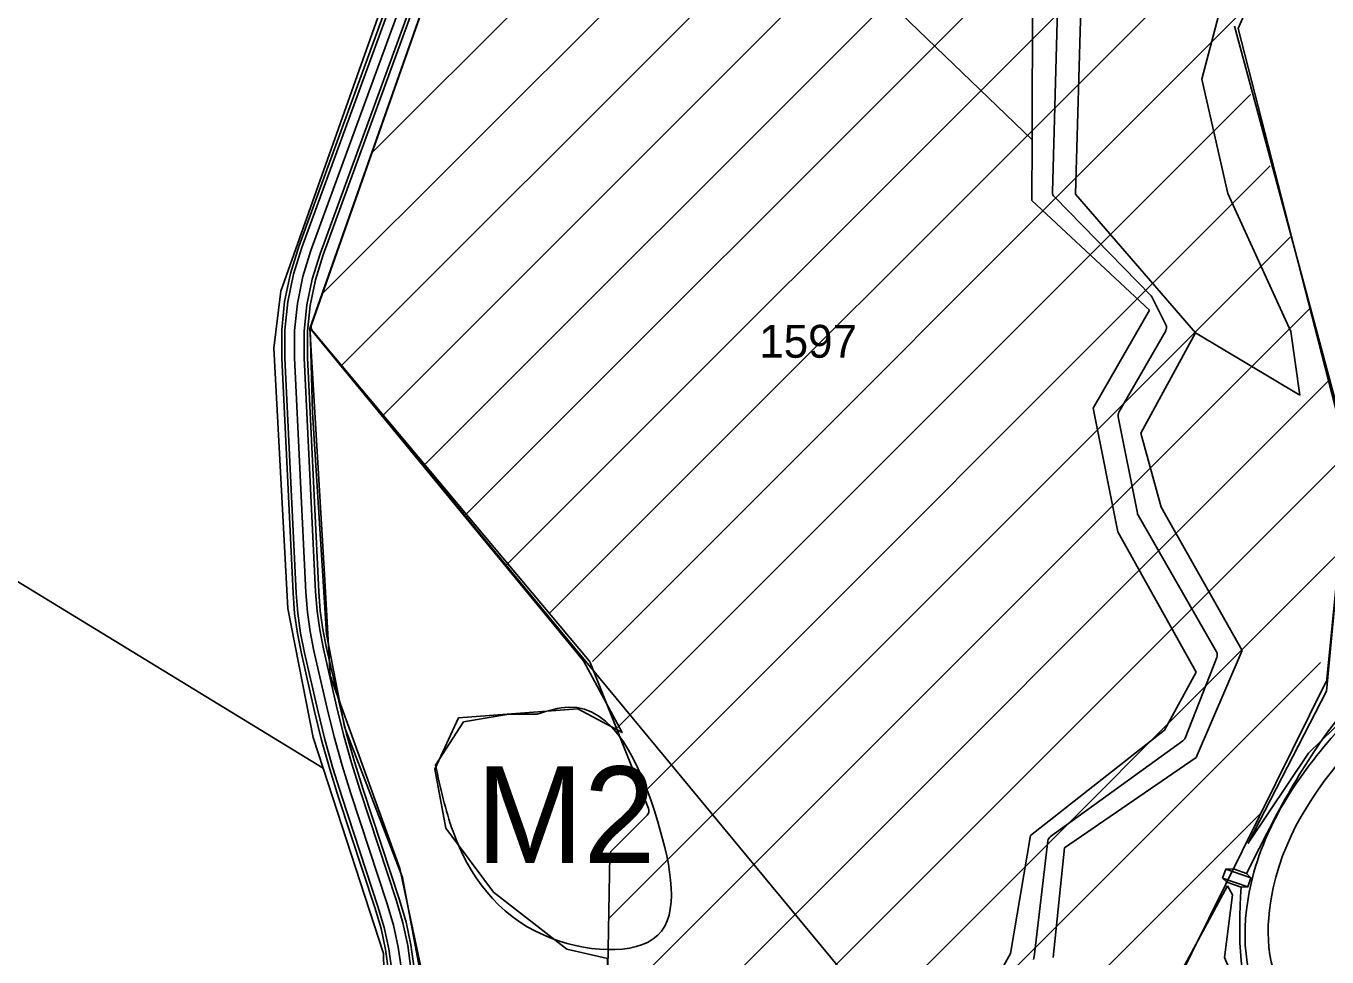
# Model space of a CAD drawing. Extents: x -510185 to -506993, y -1126306 to -1123642.
# Drawn here: x -508882.8 to -508680.9, y -1124887 to -1124742.5 of the extents above; entities that cross this region are included whole.
import ezdxf

# ---------------------------------------------------------------- set-up
doc = ezdxf.new("R2010")
doc.units = 0
for name, color, linetype in [('mokrad', 7, 'Continuous'), ('nadrze', 7, 'Continuous'), ('navrh', 7, 'Continuous'), ('parcelni hranice', 7, 'Continuous'), ('u_cesta45', 7, 'Continuous'), ('u_osa45', 7, 'Continuous'), ('u_popis', 7, 'Continuous'), ('u_stávající', 7, 'Continuous'), ('u_tok Luha', 7, 'Continuous'), ('u_vysadba', 7, 'Continuous'), ('ˇ2', 7, 'Continuous')]:
    doc.layers.add(name, color=color, linetype=linetype)

msp = doc.modelspace()

# ---------------------------------------------------------------- linework, layer by layer
at = {"layer": 'mokrad'}
for q in [(-508819.23, -1124857.2), (-508819.23, -1124857.2), (-508814.9, -1124850.45), (-508814.9, -1124850.45)]:
    msp.add_line((-508814.9, -1124850.45), q, dxfattribs=at)
msp.add_lwpolyline([(-508803.43, -1124849.25), (-508807.85, -1124849.25), (-508814.9, -1124850.45)], dxfattribs=at)
msp.add_lwpolyline([(-508803.43, -1124849.25), (-508807.85, -1124849.25), (-508814.9, -1124850.45)], dxfattribs=at)
msp.add_spline([(-508819.23, -1124857.2), (-508816.51, -1124867.47), (-508802.36, -1124883.59), (-508784.74, -1124883.59), (-508784.74, -1124865.97), (-508798.56, -1124848.18), (-508803.43, -1124849.25)], degree=3, dxfattribs=at)
msp.add_spline([(-508819.23, -1124857.2), (-508816.51, -1124867.47), (-508802.36, -1124883.59), (-508784.74, -1124883.59), (-508784.74, -1124865.97), (-508798.56, -1124848.18), (-508803.43, -1124849.25)], degree=3, dxfattribs=at)
at = {"layer": 'nadrze'}
for points in [[(-508694.23, -1124876.14), (-508690.87, -1124897.1), (-508667.86, -1124904.35), (-508650.57, -1124886.83), (-508642.98, -1124843.87), (-508642.98, -1124820.02), (-508656.31, -1124828.74)], [(-508656.1, -1124830.1), (-508678.45, -1124850.98), (-508692.67, -1124875.57), (-508689.79, -1124896.18), (-508668.2, -1124902.98), (-508651.69, -1124886.25), (-508644.18, -1124843.77), (-508644.18, -1124822.24), (-508655.66, -1124829.75)], [(-508656.92, -1124829.22), (-508679.39, -1124850.23), (-508693.38, -1124874)], [(-508653.85, -1124832.51), (-508675.83, -1124853.06), (-508689.24, -1124876.24), (-508686.81, -1124893.66), (-508669.13, -1124899.23), (-508654.76, -1124884.67), (-508647.48, -1124843.48), (-508647.48, -1124828.34), (-508653.85, -1124832.51)]]:
    msp.add_spline(points, degree=3, dxfattribs=at)
at = {"layer": 'navrh'}
for p, q in [((-508695.41, -1124873.29), (-508696.59, -1124873.3)), ((-508693.38, -1124874), (-508692.7, -1124874.66)), ((-508697.09, -1124874.71), (-508696.44, -1124875.36)), ((-508694.23, -1124876.14), (-508693.19, -1124876.08))]:
    msp.add_line(p, q, dxfattribs=at)
msp.add_lwpolyline([(-508697.09, -1124874.71), (-508696.59, -1124873.3), (-508692.7, -1124874.66), (-508693.19, -1124876.08)], close=True, dxfattribs=at)
for points in [[(-508695.41, -1124873.29), (-508693.38, -1124874)], [(-508694.23, -1124876.14), (-508696.44, -1124875.36)]]:
    msp.add_lwpolyline(points, dxfattribs=at)
at = {"layer": 'parcelni hranice'}
for p, q in [((-508801.86, -1124687.67), (-508726.64, -1124760.11)), ((-508700.29, -1124750.72), (-508685.93, -1124695.92)), ((-508807.26, -1124699.99), (-508838.66, -1124789.41)), ((-508819.64, -1124717.08), (-508843.22, -1124783.6)), ((-508726.64, -1124760.11), (-508726.57, -1124730.43)), ((-508718.91, -1124733.58), (-508719.91, -1124768.57)), ((-508696.28, -1124768.46), (-508700.29, -1124750.72)), ((-508726.67, -1124769.53), (-508726.64, -1124760.11)), ((-508986.57, -1124766.14), (-508836.65, -1124857.65)), ((-508719.91, -1124768.57), (-508701.29, -1124790.09)), ((-508686.52, -1124789.88), (-508696.28, -1124768.46)), ((-508708.45, -1124786.55), (-508726.67, -1124769.53)), ((-508844.31, -1124792.46), (-508843.22, -1124783.6)), ((-508717.17, -1124801.79), (-508708.45, -1124786.55)), ((-508838.66, -1124789.41), (-508838.33, -1124802.44)), ((-508838.66, -1124789.41), (-508741.4, -1124906.94)), ((-508709.79, -1124805.66), (-508701.29, -1124790.09)), ((-508701.29, -1124790.09), (-508685.1, -1124799.75)), ((-508686.52, -1124789.88), (-508685.1, -1124799.75)), ((-508844.31, -1124792.46), (-508842.13, -1124832.86)), ((-508836.15, -1124836.84), (-508838.33, -1124802.44)), ((-508713.36, -1124820.95), (-508717.17, -1124801.79)), ((-508706.6, -1124817.16), (-508709.79, -1124805.66)), ((-508706.6, -1124817.16), (-508694.07, -1124839.37)), ((-508713.36, -1124820.95), (-508701.17, -1124842.76)), ((-508838.2, -1124852.87), (-508842.13, -1124832.86)), ((-508833.38, -1124851.24), (-508836.15, -1124836.84)), ((-508701.2, -1124855.97), (-508694.07, -1124839.37)), ((-508701.17, -1124842.76), (-508706.1, -1124851.76)), ((-508833.38, -1124851.24), (-508824.36, -1124874.6)), ((-508706.1, -1124851.76), (-508726.92, -1124868.1)), ((-508838.2, -1124852.87), (-508836.65, -1124857.65)), ((-508836.65, -1124857.65), (-508827.32, -1124886.39)), ((-508701.2, -1124855.97), (-508721.62, -1124870.03)), ((-508730, -1124886.42), (-508726.92, -1124868.1)), ((-508723.4, -1124887.06), (-508721.62, -1124870.03)), ((-508821.31, -1124890.89), (-508824.36, -1124874.6)), ((-508826.61, -1124916.99), (-508827.32, -1124886.39)), ((-508730, -1124886.42), (-508741.4, -1124906.94))]:
    msp.add_line(p, q, dxfattribs=at)
at = {"layer": 'u_cesta45'}
for points in [[(-508826.52, -1124889.11), (-508826.99, -1124885.79), (-508827.69, -1124882.52), (-508828.64, -1124879.27), (-508834.27, -1124862.21), (-508835.65, -1124857.79), (-508836.9, -1124853.32), (-508838, -1124848.83), (-508840.05, -1124839.85), (-508840.66, -1124836.77), (-508841.09, -1124833.64), (-508841.33, -1124830.51), (-508843.1, -1124794.02), (-508843.09, -1124789.63), (-508842.64, -1124785.22), (-508841.76, -1124780.87), (-508840.46, -1124776.68), (-508812.95, -1124701.42)], [(-508826.02, -1124889.06), (-508826.5, -1124885.71), (-508827.21, -1124882.4), (-508828.16, -1124879.12), (-508833.79, -1124862.05), (-508835.17, -1124857.65), (-508836.41, -1124853.19), (-508837.51, -1124848.71), (-508839.56, -1124839.74), (-508840.16, -1124836.69), (-508840.59, -1124833.58), (-508840.83, -1124830.48), (-508842.6, -1124794.01), (-508842.59, -1124789.66), (-508842.15, -1124785.29), (-508841.27, -1124780.99), (-508839.98, -1124776.84), (-508812.48, -1124701.59)], [(-508823.04, -1124888.75), (-508823.54, -1124885.18), (-508824.3, -1124881.66), (-508825.29, -1124878.23), (-508830.94, -1124861.13), (-508832.29, -1124856.8), (-508833.51, -1124852.43), (-508834.59, -1124848.02), (-508836.62, -1124839.12), (-508837.2, -1124836.19), (-508837.6, -1124833.26), (-508837.84, -1124830.29), (-508839.6, -1124793.94), (-508839.59, -1124789.81), (-508839.18, -1124785.74), (-508838.36, -1124781.74), (-508837.14, -1124777.8), (-508809.65, -1124702.59)], [(-508822.54, -1124888.69), (-508823.05, -1124885.09), (-508823.81, -1124881.54), (-508824.82, -1124878.08), (-508830.46, -1124860.98), (-508831.81, -1124856.66), (-508833.03, -1124852.31), (-508834.1, -1124847.9), (-508836.13, -1124839.01), (-508836.71, -1124836.11), (-508837.11, -1124833.21), (-508837.34, -1124830.26), (-508839.1, -1124793.92), (-508839.09, -1124789.84), (-508838.68, -1124785.82), (-508837.88, -1124781.86), (-508836.67, -1124777.96), (-508809.18, -1124702.75)]]:
    msp.add_lwpolyline(points, dxfattribs=at)
at = {"layer": 'u_osa45'}
msp.add_lwpolyline([(-508824.53, -1124888.9), (-508825.02, -1124885.44), (-508825.75, -1124882.03), (-508826.73, -1124878.68), (-508832.36, -1124861.59), (-508833.73, -1124857.22), (-508834.96, -1124852.81), (-508836.05, -1124848.37), (-508838.09, -1124839.43), (-508838.68, -1124836.44), (-508839.1, -1124833.42), (-508839.33, -1124830.39), (-508841.1, -1124793.97), (-508841.09, -1124789.73), (-508840.66, -1124785.52), (-508839.82, -1124781.36), (-508838.56, -1124777.32), (-508811.07, -1124702.09)], dxfattribs=at)
at = {"layer": 'u_stávající'}
for p, q in [((-508829.09, -1124762.15), (-508690.79, -1124623.85)), ((-508836.74, -1124783.95), (-508699.97, -1124647.18)), ((-508833.86, -1124795.21), (-508696.47, -1124657.82)), ((-508827.46, -1124802.95), (-508692.52, -1124668.01)), ((-508821.05, -1124810.69), (-508686.76, -1124676.4)), ((-508814.47, -1124818.25), (-508681.73, -1124685.5)), ((-508808.25, -1124826.16), (-508678.68, -1124696.6)), ((-508801.57, -1124833.63), (-508682.87, -1124714.93)), ((-508822.96, -1124744.7), (-508819.51, -1124734.91)), ((-508794.87, -1124841.07), (-508694.76, -1124740.96)), ((-508838.47, -1124788.87), (-508822.96, -1124744.7)), ((-508791, -1124851.34), (-508692.75, -1124753.09)), ((-508787.13, -1124861.62), (-508689.68, -1124764.17)), ((-508792.43, -1124881.06), (-508686.62, -1124775.25)), ((-508794.55, -1124897.32), (-508683.55, -1124786.33)), ((-508795.39, -1124840.99), (-508838.29, -1124789.85)), ((-508796.64, -1124913.55), (-508680.49, -1124797.4)), ((-508795.52, -1124926.58), (-508677.44, -1124808.49)), ((-508677.42, -1124808.96), (-508680.89, -1124843.86)), ((-508832.72, -1124977.92), (-508679.67, -1124824.86)), ((-508835.95, -1124995.29), (-508681.89, -1124841.23)), ((-508786.18, -1124863.89), (-508795.22, -1124841.27)), ((-508680.99, -1124844.2), (-508705.43, -1124893.47)), ((-508838.07, -1125011.55), (-508691.31, -1124864.79)), ((-508791.88, -1124870.45), (-508786.4, -1124864.97)), ((-508792.55, -1124891.63), (-508792.17, -1124871.14))]:
    msp.add_line(p, q, dxfattribs=at)
msp.add_lwpolyline([(-508695.23, -1124742.47), (-508686.36, -1124775.45), (-508677.45, -1124808.6)], dxfattribs=at)
for centre, start, end in [((-508837.53, -1124789.2), 160.6512, 219.9932), ((-508796.15, -1124841.64), 21.8014, 39.9932), ((-508681.88, -1124843.76), 333.6157, 354.3229), ((-508787.1, -1124864.26), 315, 21.8014), ((-508791.17, -1124871.16), 135, 178.9391)]:
    msp.add_arc(centre, 1, start, end, dxfattribs=at)
at = {"layer": 'u_tok Luha'}
for p, q in [((-508723.48, -1124768.27), (-508722.47, -1124731.29)), ((-508708.19, -1124784.36), (-508723.19, -1124768.99)), ((-508705.89, -1124788.83), (-508708.01, -1124784.61)), ((-508713.17, -1124802.42), (-508705.92, -1124789.78)), ((-508710.31, -1124818.07), (-508713.29, -1124803.11)), ((-508698.04, -1124839.62), (-508710.2, -1124818.37)), ((-508702.9, -1124852.97), (-508697.98, -1124840.48)), ((-508723.79, -1124868.25), (-508703.25, -1124853.42)), ((-508726.33, -1124886.95), (-508724.2, -1124868.95))]:
    msp.add_line(p, q, dxfattribs=at)
for centre, start, end in [((-508722.48, -1124768.29), 178.4368, 224.326), ((-508708.9, -1124785.06), 26.5651, 44.326), ((-508706.79, -1124789.28), 330.1541, 26.5651), ((-508712.31, -1124802.92), 150.1541, 191.2577), ((-508709.33, -1124817.88), 191.2577, 209.7864), ((-508698.91, -1124840.11), 338.4735, 29.7864), ((-508703.83, -1124852.6), 305.8377, 338.4735), ((-508723.21, -1124869.06), 125.8377, 173.264), ((-508727.32, -1124886.84), 330.4804, 353.264)]:
    msp.add_arc(centre, 1, start, end, dxfattribs=at)
at = {"layer": 'u_vysadba'}
for p, q in [((-508807.26, -1124699.99), (-508838.66, -1124789.41)), ((-508838.66, -1124789.41), (-508838.33, -1124802.44)), ((-508838.33, -1124802.44), (-508836.15, -1124836.84)), ((-508836.15, -1124836.84), (-508833.38, -1124851.24)), ((-508833.38, -1124851.24), (-508824.36, -1124874.6)), ((-508824.36, -1124874.6), (-508821.31, -1124890.89))]:
    msp.add_line(p, q, dxfattribs=at)
msp.add_lwpolyline([(-508677.25, -1124702.46), (-508694.65, -1124742.85), (-508677.56, -1124809.66), (-508680.98, -1124845.7), (-508693.1, -1124869.31), (-508683.78, -1124855.33), (-508660.47, -1124832.65), (-508647.73, -1124822.08), (-508639.7, -1124818.35), (-508639.7, -1124824.88), (-508644.94, -1124863.72), (-508650.22, -1124889.82), (-508658.92, -1124898.21), (-508667.31, -1124905.36), (-508677.87, -1124906.29), (-508687.82, -1124901.63), (-508694.34, -1124907.84), (-508689.37, -1124919.34), (-508689.37, -1124928.04), (-508690.92, -1124930.84), (-508573.47, -1124904.74), (-508570.05, -1124783.24), (-508567.26, -1124695.93)], dxfattribs=at)
for points in [[(-508827.62, -1124949.9), (-508816.5, -1124937.64), (-508797.97, -1124933.37), (-508794.55, -1124929.09), (-508797.4, -1124906.29), (-508792.56, -1124892.6), (-508792.56, -1124887.19), (-508798.83, -1124885.76), (-508810.23, -1124876.92), (-508817.64, -1124866.95), (-508819.35, -1124857.82), (-508815.65, -1124849.84), (-508797.12, -1124848.42), (-508790.28, -1124852.12), (-508796.26, -1124841.01), (-508838.66, -1124789.41), (-508806.81, -1124698.75), (-508838.74, -1124789.41), (-508836.46, -1124827.61), (-508835.6, -1124843.29), (-508824.77, -1124873.22), (-508819.92, -1124896.02), (-508821.06, -1124920.26)], [(-508696.34, -1124875.93), (-508710.68, -1124902.45), (-508703.58, -1124901.99), (-508698.8, -1124903.22), (-508693.1, -1124895.51), (-508696.8, -1124887.03), (-508695.56, -1124877.32)]]:
    msp.add_lwpolyline(points, close=True, dxfattribs=at)

# ---------------------------------------------------------------- texts
at = {"layer": 'u_popis'}
msp.add_text('M2', height=15, dxfattribs=at).set_placement((-508812.96, -1124872.38))
at = {"layer": 'ˇ2'}
msp.add_text('1597', height=5.1, dxfattribs=at).set_placement((-508768.99, -1124793.95))

doc.saveas('drawing.dxf')
